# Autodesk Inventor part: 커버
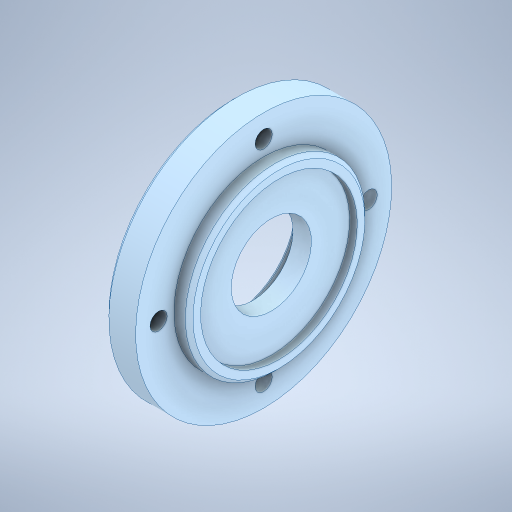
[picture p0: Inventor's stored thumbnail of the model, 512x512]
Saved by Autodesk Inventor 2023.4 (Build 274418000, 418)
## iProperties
Created: 2024-04
Part Number: 커버
Material: 알루미늄 6061
Document SubType Name: Modeling
Designer: Edu03
Density: 2.7 g/cm^3
Appearance: 기본값
Author: jhkim
Sending System: Autodesk Inventor 2025
Preprocessor: ST-DEVELOPER v20
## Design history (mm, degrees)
feature "솔리드1"
node "솔리드2"
